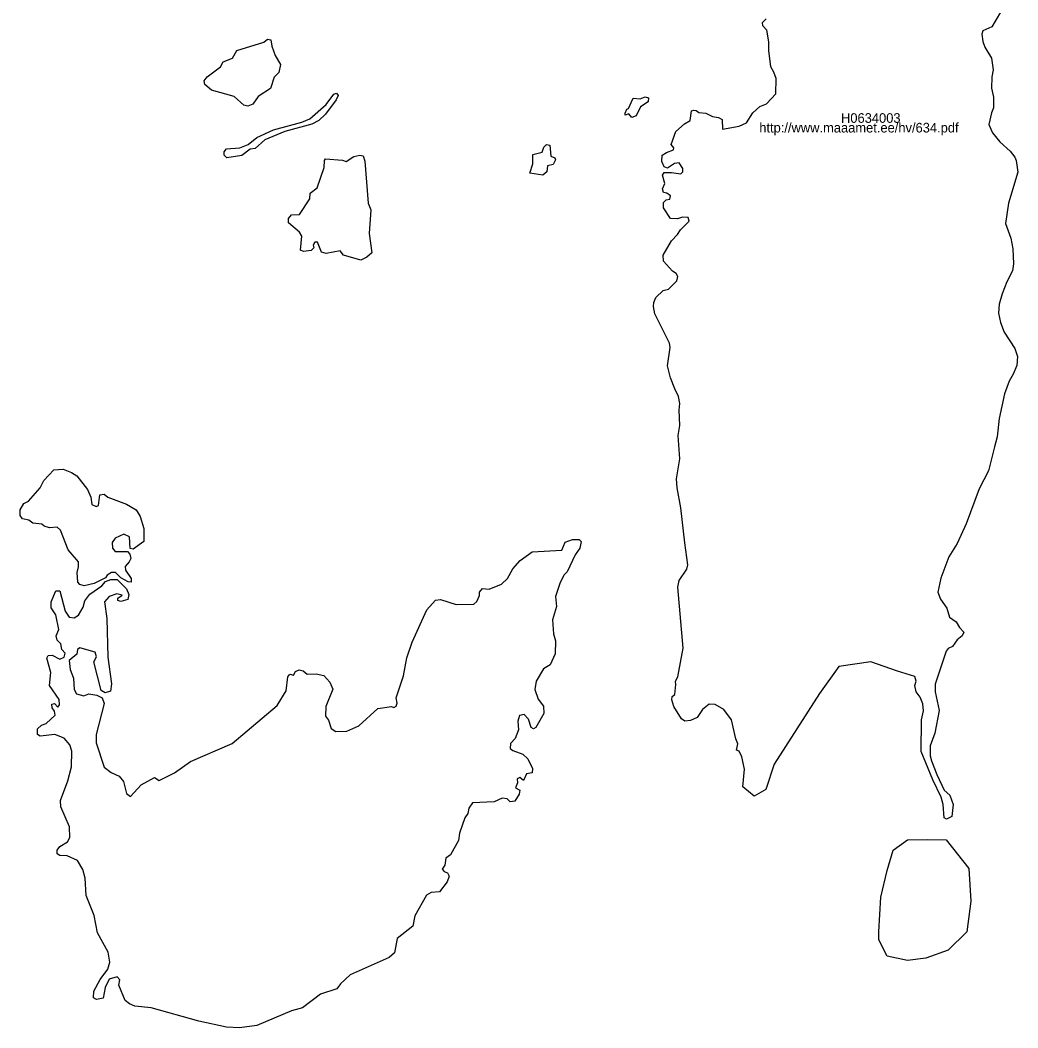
# Model space of a CAD drawing. Extents: x 369010 to 739155, y 6377141 to 6634081.
# Drawn here: x 457245 to 459831, y 6475832 to 6478444 of the extents above; entities that cross this region are included whole.
import ezdxf

# ---------------------------------------------------------------- set-up
doc = ezdxf.new("R2010")
doc.units = 0
for name, color, linetype in [('H_LINK', 7, 'Continuous'), ('H_PIIR', 7, 'Continuous'), ('H_TUNNUS', 7, 'Continuous')]:
    doc.layers.add(name, color=color, linetype=linetype)

msp = doc.modelspace()

# ---------------------------------------------------------------- linework, layer by layer
at = {"layer": 'H_PIIR'}
msp.add_lwpolyline([(459797.8501, 6478483.9346), (459763.99, 6478427.0347), (459740.7701, 6478416.2046), (459738.06, 6478408.0747), (459740.38, 6478388.3247), (459745.7999, 6478373.6246), (459762.6401, 6478345.3546), (459767.2801, 6478315.1647), (459763.41, 6478297.3646), (459763.03, 6478267.5546), (459768.4401, 6478244.7147), (459768.06, 6478216.4547), (459762.45, 6478203.6847), (459756.2499, 6478173.8846), (459765.16, 6478151.8147), (459784.5099, 6478128.5946), (459811.21, 6478104.5947), (459823.01, 6478088.7246), (459826.89, 6478080.5946), (459831.14, 6478049.6247), (459806.9499, 6477969.8846), (459798.8299, 6477916.4747), (459812.96, 6477878.5346), (459818.38, 6477851.0446), (459819.92, 6477811.9547), (459817.6, 6477794.5347), (459802.5101, 6477765.8847), (459790.7, 6477734.1447), (459782.57, 6477708.2047), (459780.64, 6477684.2046), (459786.05, 6477660.5946), (459796.1201, 6477635.4347), (459823.02, 6477592.4746), (459830.37, 6477572.3446), (459828.82, 6477549.1146), (459819.35, 6477525.8847), (459808.51, 6477508.0846), (459796.51, 6477475.1746), (459782.96, 6477411.3046), (459777.5499, 6477363.6947), (459770.97, 6477338.1447), (459754.71, 6477275.8246), (459731.1, 6477228.9946), (459697.24, 6477138.0247), (459674.02, 6477086.9246), (459651.95, 6477052.4746), (459631.44, 6476997.5146), (459623.9, 6476961.5147), (459630.86, 6476942.9347), (459647.1199, 6476919.3147), (459654.0899, 6476896.4846), (459671.12, 6476884.0947), (459679.6301, 6476869.3846), (459691.43, 6476857.3846), (459686.79, 6476847.7046), (459673.6299, 6476837.2546), (459662.02, 6476820.6147), (459650.41, 6476814.8046), (459644.9901, 6476807.8346), (459616.93, 6476722.6747), (459616.5399, 6476702.5447), (459627.38, 6476654.5447), (459615.9599, 6476595.7147), (459603.58, 6476562.4246), (459603.58, 6476537.2646), (459607.06, 6476524.1047), (459620.79, 6476488.1046), (459639.7601, 6476447.8446), (459655.2399, 6476435.0746), (459663.76, 6476411.0747), (459659.8899, 6476379.7146), (459646.34, 6476372.3647), (459640.15, 6476375.8447), (459637.4401, 6476411.0747), (459632.02, 6476430.0447), (459611.12, 6476474.5547), (459580.54, 6476548.1046), (459581.13, 6476629.7747), (459586.93, 6476653.7746), (459585.0001, 6476671.9647), (459578.0301, 6476688.9946), (459567.5799, 6476702.9347), (459564.48, 6476718.8046), (459567.38, 6476730.8047), (459563.9, 6476742.8047), (459519.3386, 6476756.7352), (459450.5468, 6476780.5478), (459367.2029, 6476768.6415), (459316.932, 6476698.5268), (459199.1722, 6476515.4909), (459178.0254, 6476449.818), (459147.5983, 6476432.62), (459118.4941, 6476456.4326), (459123.07, 6476502.4146), (459116.1, 6476534.5447), (459108.75, 6476549.2546), (459102.17, 6476551.1847), (459105.65, 6476568.2246), (459099.84, 6476580.6047), (459089.39, 6476630.1546), (459068.88, 6476656.8647), (459047.01, 6476670.0247), (459031.5299, 6476670.8047), (459014.11, 6476656.8647), (458999.7899, 6476636.3546), (458982.38, 6476628.2246), (458967.67, 6476627.0646), (458959.15, 6476632.8646), (458939.7999, 6476664.6046), (458933.9999, 6476682.4146), (458935.1599, 6476690.9347), (458942.1199, 6476695.9647), (458944.83, 6476721.8946), (458944.06, 6476730.8047), (458950.2501, 6476741.6347), (458963.9999, 6476815.5747), (458949.86, 6476973.8946), (458953.7401, 6476991.3146), (458973.47, 6477021.1146), (458976.1801, 6477032.3447), (458967.67, 6477088.8646), (458957.99, 6477179.8246), (458948.31, 6477231.6946), (458946.38, 6477254.5347), (458954.7, 6477306.7946), (458950.8301, 6477367.1747), (458955.08, 6477393.5046), (458953.7301, 6477433.3747), (458954.8901, 6477450.0146), (458951.79, 6477468.5947), (458941.73, 6477487.9446), (458930.89, 6477516.5947), (458923.1501, 6477547.9446), (458930.31, 6477595.5547), (458927.99, 6477606.3946), (458890.2501, 6477683.0446), (458886.7701, 6477701.6246), (458887.54, 6477712.4546), (458892.96, 6477724.8447), (458912.31, 6477743.0346), (458925.8599, 6477746.9146), (458947.53, 6477768.5847), (458950.2401, 6477779.4246), (458945.21, 6477787.1647), (458936.12, 6477793.3646), (458912.51, 6477819.6846), (458912.1199, 6477834.3947), (458933.4099, 6477871.9447), (458949.0801, 6477888.2047), (458956.43, 6477900.2047), (458978.88, 6477923.0446), (458976.95, 6477932.7246), (458962.2399, 6477933.4946), (458948.69, 6477928.8446), (458930.4999, 6477930.0146), (458913.08, 6477957.1046), (458913.08, 6477971.0446), (458919.6601, 6477978.0046), (458928.9501, 6477980.3347), (458931.2701, 6477988.4647), (458921.02, 6477995.8146), (458912.89, 6477997.3646), (458910.18, 6478006.6546), (458915.99, 6478020.9746), (458910.57, 6478041.8746), (458914.83, 6478048.8446), (458933.3999, 6478049.2347), (458957.7901, 6478045.7447), (458963.21, 6478051.1646), (458962.8199, 6478059.2946), (458953.53, 6478074.3947), (458941.15, 6478072.8447), (458922.95, 6478060.4546), (458914.4401, 6478063.5547), (458908.6299, 6478077.8747), (458909.41, 6478094.1347), (458920.2501, 6478101.1047), (458938.82, 6478108.0747), (458939.6, 6478113.1047), (458932.63, 6478122.0046), (458945.0201, 6478155.2947), (458967.27, 6478175.4247), (458981.6, 6478183.5547), (458985.08, 6478208.7146), (458991.2701, 6478211.0346), (458997.4599, 6478209.4947), (459004.04, 6478204.8447), (459022.2299, 6478202.9146), (459039.6501, 6478194.0047), (459055.52, 6478192.0747), (459065.2, 6478186.2646), (459065.5799, 6478161.4947), (459108.76, 6478168.9246), (459128.12, 6478178.2146), (459143.9799, 6478203.7647), (459162.18, 6478220.0247), (459179.98, 6478227.3747), (459203.5901, 6478252.9246), (459204.94, 6478292.8046), (459199.13, 6478309.4447), (459191, 6478322.9946), (459186.1699, 6478365.5746), (459186.1699, 6478388.0246), (459180.3599, 6478418.2246), (459169.91, 6478429.0646), (459169.5301, 6478437.9647), (459179.1999, 6478447.2547)], dxfattribs=at)
for points in [[(457886.515, 6478395.0093), (457895.2867, 6478393.0233), (457897.2728, 6478376.3073), (457906.21, 6478352.3093), (457920.1124, 6478329.1386), (457915.4783, 6478308.2852), (457903.562, 6478295.8723), (457894.1283, 6478266.7436), (457862.517, 6478246.2211), (457848.118, 6478226.1952), (457835.0433, 6478220.7336), (457825.2785, 6478223.3816), (457799.7909, 6478245.8902), (457740.8715, 6478262.937), (457724.1556, 6478276.8394), (457722.5006, 6478286.9352), (457730.2793, 6478297.0309), (457764.704, 6478323.0151), (457771.3243, 6478336.0898), (457795.3223, 6478345.8546), (457806.9076, 6478365.2185), (457877.2467, 6478387.2305)], [(458065.0939, 6478255.1585), (458069.3969, 6478249.0348), (458064.7628, 6478237.4494), (458036.7927, 6478200.542), (458019.7457, 6478184.3227), (458001.5403, 6478174.227), (457931.6975, 6478155.6904), (457879.0674, 6478133.6784), (457854.7383, 6478111.1699), (457841.3325, 6478110.0113), (457820.1479, 6478093.4609), (457781.42, 6478087.5029), (457773.9723, 6478094.123), (457773.9723, 6478103.0603), (457780.2614, 6478110.8388), (457814.6863, 6478113.487), (457836.3672, 6478121.5966), (457858.7104, 6478139.4711), (457901.7413, 6478159.6625), (457975.0596, 6478179.3575), (457996.4096, 6478188.2948), (458038.1166, 6478225.3677), (458058.6391, 6478252.5103)], [(458864.9747, 6478245.5591), (458874.2428, 6478242.7456), (458872.5878, 6478232.6498), (458853.2239, 6478219.575), (458841.6386, 6478195.9079), (458830.8807, 6478192.1014), (458822.7711, 6478201.3695), (458813.3374, 6478197.5631), (458813.3374, 6478202.8591), (458818.137, 6478213.2858), (458822.2747, 6478214.941), (458833.8599, 6478242.0836), (458852.0653, 6478240.0976)], [(458609.602, 6478121.5966), (458618.2083, 6478120.1071), (458620.8563, 6478091.475), (458630.952, 6478086.8408), (458632.4416, 6478081.7103), (458626.6488, 6478070.125), (458612.4155, 6478066.3183), (458610.4296, 6478051.2575), (458600.0027, 6478041.9892), (458566.7364, 6478047.7818), (458573.6876, 6478071.2834), (458574.3496, 6478096.1091), (458598.0167, 6478101.5707), (458602.9818, 6478115.142)], [(458127.9853, 6477822.0344), (458083.1338, 6477834.7782), (458074.5276, 6477846.0324), (458038.7786, 6477839.0814), (458026.6969, 6477842.226), (458016.2702, 6477868.5411), (458009.319, 6477868.5411), (458004.6849, 6477861.0935), (458006.6708, 6477853.8112), (457999.2232, 6477846.86), (457979.8592, 6477844.5431), (457971.7495, 6477848.0186), (457975.2252, 6477884.4294), (457969.4325, 6477894.0286), (457940.4692, 6477918.8543), (457941.1313, 6477929.6119), (457948.579, 6477939.3768), (457969.7636, 6477940.5352), (457996.4096, 6477980.4218), (457996.7407, 6477995.4826), (458015.277, 6478009.7159), (458033.4826, 6478061.6842), (458033.979, 6478080.5517), (458036.9582, 6478084.5238), (458080.8168, 6478081.3792), (458090.0849, 6478077.5726), (458109.9455, 6478090.6474), (458125.5027, 6478094.123), (458134.771, 6478092.6334), (458138.5776, 6478078.7312), (458147.5148, 6477969.8296), (458154.135, 6477952.4515), (458150.163, 6477890.5531), (458156.9485, 6477840.571), (458144.2047, 6477829.482)], [(457533.3295, 6476987.2323), (457525.5508, 6476987.5633), (457505.8558, 6476998.4866), (457492.6155, 6477012.389), (457481.8578, 6477012.389), (457470.9345, 6477005.4378), (457466.3004, 6476998.4866), (457437.3372, 6476983.2603), (457411.353, 6476977.9641), (457400.4297, 6476980.6121), (457394.6372, 6476987.2323), (457392.8167, 6477012.389), (457396.9542, 6477026.6223), (457396.2922, 6477039.5315), (457369.8115, 6477070.4807), (457349.951, 6477122.2835), (457341.0139, 6477129.2347), (457320.9878, 6477128.0761), (457307.4165, 6477132.0482), (457301.9549, 6477137.0134), (457278.2878, 6477140.158), (457267.6956, 6477147.4402), (457251.1452, 6477150.9157), (457245.3525, 6477159.5219), (457245.3525, 6477174.2518), (457255.2828, 6477191.2988), (457266.8681, 6477197.4223), (457297.1553, 6477231.8472), (457306.589, 6477250.5492), (457332.4077, 6477278.0229), (457356.4057, 6477279.8434), (457378.7488, 6477271.7337), (457391.989, 6477262.4654), (457420.2902, 6477227.213), (457428.7309, 6477207.8492), (457430.7171, 6477188.4851), (457442.6333, 6477183.0235), (457448.095, 6477185.8371), (457452.0671, 6477213.6418), (457462.8247, 6477215.2968), (457472.5896, 6477207.8492), (457521.0821, 6477188.9817), (457546.2388, 6477174.5827), (457556.6655, 6477157.5359), (457565.6028, 6477126.2556), (457565.9337, 6477092.8239), (457538.46, 6477072.7978), (457530.847, 6477074.2874), (457528.5299, 6477104.5747), (457514.462, 6477111.8568), (457491.6225, 6477101.4301), (457484.0093, 6477089.8448), (457484.6713, 6477075.446), (457491.788, 6477067.0052), (457523.2337, 6477066.1777), (457529.8538, 6477059.8886), (457532.1709, 6477048.7998), (457528.1988, 6477039.5315), (457517.7721, 6477027.7807), (457518.5996, 6477018.1815), (457533.3295, 6476996.8315)], [(457794.5164, 6476568.6161), (457911.6716, 6476667.6441), (457935.1732, 6476705.2135), (457939.3108, 6476741.6244), (457943.9449, 6476748.2444), (457953.7096, 6476745.9274), (457959.1712, 6476755.6922), (457968.7704, 6476759.8298), (457978.8662, 6476757.1818), (457989.2929, 6476748.2444), (458012.1325, 6476749.072), (458032.324, 6476744.7689), (458048.3778, 6476727.722), (458055.6602, 6476709.8476), (458037.4547, 6476664.6649), (458036.7927, 6476639.8394), (458044.9023, 6476629.4127), (458051.026, 6476607.7316), (458063.7698, 6476599.9529), (458092.071, 6476601.1115), (458123.3513, 6476614.3517), (458172.5059, 6476659.2033), (458207.5927, 6476664.996), (458214.2129, 6476661.8515), (458220.0055, 6476665.327), (458222.8192, 6476673.4366), (458220.0055, 6476687.5045), (458238.7075, 6476743.9414), (458247.1483, 6476790.779), (458261.0505, 6476831.493), (458299.4475, 6476915.5691), (458321.7905, 6476940.7257), (458334.6999, 6476941.8842), (458375.2483, 6476929.1404), (458421.424, 6476929.8024), (458429.2027, 6476937.25), (458435.6573, 6476952.3109), (458436.1539, 6476961.5791), (458443.7669, 6476970.5163), (458461.3103, 6476968.5303), (458492.9217, 6476981.7707), (458508.479, 6476996.5004), (458522.3814, 6477021.6571), (458540.9177, 6477042.8416), (458572.6946, 6477065.6811), (458649.3229, 6477069.9843), (458658.2601, 6477090.5068), (458676.9621, 6477097.9544), (458693.8436, 6477097.9544), (458699.3051, 6477092.8239), (458695.8295, 6477075.1149), (458683.9133, 6477058.0681), (458663.3908, 6477013.8783), (458654.7846, 6477005.2723), (458644.0268, 6476983.5912), (458632.7725, 6476949.9938), (458635.0896, 6476924.0097), (458624.9938, 6476889.2539), (458627.3109, 6476853.174), (458632.7725, 6476834.6376), (458631.945, 6476801.7023), (458618.8701, 6476773.0701), (458601.3268, 6476762.6434), (458582.7904, 6476730.039), (458579.6458, 6476708.689), (458588.252, 6476684.029), (458601.3268, 6476665.327), (458602.9818, 6476646.4595), (458581.9629, 6476610.7107), (458575.5081, 6476606.9041), (458570.0464, 6476610.3796), (458563.0954, 6476631.7296), (458551.841, 6476644.1425), (458539.7593, 6476640.9979), (458535.6217, 6476627.0956), (458536.7802, 6476604.2561), (458528.174, 6476582.0784), (458516.5888, 6476568.5071), (458515.4302, 6476556.2599), (458522.0504, 6476550.7983), (458548.0344, 6476541.53), (458560.7784, 6476529.4483), (458573.3567, 6476503.9605), (458572.5292, 6476492.7063), (458557.4681, 6476490.3893), (458550.186, 6476473.3423), (458540.4213, 6476480.6246), (458533.4701, 6476477.6455), (458534.6286, 6476467.2188), (458528.836, 6476453.6473), (458540.0902, 6476447.8547), (458538.4352, 6476437.2625), (458527.181, 6476419.5535), (458515.5956, 6476417.5676), (458507.1551, 6476425.6772), (458494.4111, 6476427.3322), (458473.8886, 6476417.5676), (458417.9483, 6476415.2505), (458408.1836, 6476401.3481), (458405.5356, 6476386.9493), (458398.0878, 6476376.1915), (458384.1856, 6476336.6361), (458381.041, 6476316.9411), (458360.3529, 6476280.5302), (458348.4366, 6476271.924), (458346.1196, 6476253.7186), (458339.4995, 6476243.2919), (458344.4645, 6476237.1682), (458353.0708, 6476233.6925), (458356.8774, 6476225.0863), (458351.9123, 6476210.0255), (458332.5483, 6476184.5379), (458310.5362, 6476182.8829), (458298.7854, 6476175.6007), (458268.0017, 6476122.1429), (458263.0366, 6476095.0002), (458222.8192, 6476062.8925), (458215.7025, 6476026.1506), (458202.1312, 6476013.7377), (458100.8427, 6475969.2172), (458075.6861, 6475945.5502), (458066.4178, 6475932.4753), (458023.7178, 6475918.904), (457977.5423, 6475883.9827), (457948.4136, 6475876.204), (457858.8759, 6475837.4761), (457813.5277, 6475831.6833), (457780.0959, 6475833.6695), (457708.1018, 6475849.2267), (457585.1323, 6475883.9827), (457542.7632, 6475887.7892), (457528.8608, 6475893.7474), (457517.6066, 6475902.1881), (457500.8908, 6475942.4056), (457503.7042, 6475955.9769), (457497.0841, 6475964.0865), (457475.7341, 6475957.9628), (457465.8038, 6475935.951), (457460.6733, 6475908.8082), (457443.2954, 6475905.3327), (457435.8476, 6475909.1393), (457436.6751, 6475927.0136), (457452.5635, 6475957.1353), (457472.755, 6475983.4506), (457477.3892, 6476001.656), (457473.086, 6476027.9711), (457445.9434, 6476078.2843), (457437.5026, 6476123.3014), (457416.6492, 6476174.4421), (457413.8356, 6476219.2937), (457408.043, 6476242.4642), (457393.8097, 6476265.3038), (457367.3289, 6476277.7166), (457348.1305, 6476278.2132), (457341.0139, 6476283.1782), (457341.0139, 6476292.1156), (457348.4615, 6476301.3837), (457368.1565, 6476313.7965), (457373.9492, 6476325.0507), (457373.2872, 6476352.8555), (457350.4476, 6476404.3272), (457349.6201, 6476421.0431), (457368.984, 6476471.6873), (457378.2522, 6476508.0983), (457379.4109, 6476549.1433), (457373.9492, 6476565.0316), (457359.2193, 6476582.575), (457335.2211, 6476592.5053), (457297.3207, 6476587.5401), (457290.3697, 6476592.5053), (457290.7006, 6476606.5732), (457300.4653, 6476616.1724), (457312.3816, 6476620.4754), (457336.3797, 6476642.4874), (457334.0627, 6476652.5832), (457327.939, 6476661.5204), (457327.6081, 6476670.4577), (457334.5593, 6476672.2782), (457342.9998, 6476663.0099), (457347.303, 6476668.8027), (457346.4755, 6476683.2015), (457321.6498, 6476719.1157), (457324.7944, 6476752.5476), (457314.6986, 6476789.9515), (457318.1743, 6476796.5717), (457327.939, 6476798.2268), (457348.4615, 6476787.6344), (457359.2193, 6476792.434), (457362.3639, 6476802.8609), (457353.0956, 6476812.129), (457351.1097, 6476827.5209), (457341.3448, 6476836.4581), (457339.0277, 6476848.0434), (457345.4824, 6476864.4284), (457338.2002, 6476901.9976), (457325.4565, 6476920.5342), (457325.4565, 6476935.9261), (457338.0348, 6476964.7237), (457347.9651, 6476964.7237), (457362.0328, 6476911.597), (457372.7906, 6476896.5362), (457385.2034, 6476895.0466), (457396.7888, 6476901.1701), (457408.8705, 6476922.0237), (457412.6771, 6476938.7396), (457425.7518, 6476956.1175), (457457.3631, 6476977.4675), (457466.6313, 6476988.7217), (457480.6992, 6476994.0179), (457496.5876, 6476993.687), (457521.2476, 6476970.0199), (457526.7093, 6476955.29), (457524.3922, 6476941.8842), (457505.8558, 6476937.25), (457498.0771, 6476939.8982), (457498.9046, 6476946.0217), (457509.6624, 6476953.8004), (457496.0912, 6476956.945), (457476.3962, 6476950.3249), (457463.6522, 6476936.4225), (457469.7759, 6476892.5639), (457472.2585, 6476792.434), (457482.5197, 6476723.9153), (457479.5408, 6476704.5515), (457465.9693, 6476700.2483), (457455.046, 6476706.041), (457436.5097, 6476780.3523), (457443.4609, 6476793.9236), (457439.9852, 6476805.5089), (457399.7677, 6476816.4322), (457394.3061, 6476812.129), (457392.3201, 6476800.0472), (457372.294, 6476784.1589), (457374.9422, 6476760.9884), (457383.8793, 6476738.4798), (457385.038, 6476709.1856), (457391.1615, 6476697.4348), (457410.1946, 6476692.8007), (457423.7659, 6476697.4348), (457444.2884, 6476693.9591), (457458.1906, 6476687.5045), (457462.8247, 6476672.2782), (457441.9713, 6476592.1742), (457441.9713, 6476570.9897), (457462.8247, 6476507.7672), (457481.3613, 6476493.8649), (457501.8837, 6476484.1001), (457513.4691, 6476470.6943), (457520.9167, 6476438.9176), (457531.0124, 6476431.1389), (457558.6516, 6476462.0881), (457593.904, 6476481.121), (457605.4892, 6476472.5148), (457645.2911, 6476492.416), (457686.5662, 6476522.5785)], [(459476.3299, 6476170.7467), (459492.205, 6476239.5385), (459508.08, 6476292.4553), (459545.1217, 6476318.9136), (459595.9218, 6476320.2366), (459645.6636, 6476318.9136), (459703.8721, 6476244.8302), (459709.1637, 6476160.1633), (459698.5804, 6476080.7882), (459650.9553, 6476033.1631), (459592.7468, 6476011.9964), (459545.1217, 6476006.7047), (459492.205, 6476017.288), (459471.0383, 6476059.6215), (459471.0383, 6476080.7882)]]:
    msp.add_lwpolyline(points, close=True, dxfattribs=at)

# ---------------------------------------------------------------- texts
at = {"layer": 'H_LINK'}
msp.add_text('http://www.maaamet.ee/hv/634.pdf', height=25, dxfattribs=at).set_placement((459160.9973, 6478152.8533))
at = {"layer": 'H_TUNNUS'}
msp.add_text('H0634003', height=25, dxfattribs=at).set_placement((459372.8519, 6478177.8533))

doc.saveas('drawing.dxf')
